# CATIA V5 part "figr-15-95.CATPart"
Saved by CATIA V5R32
Part number: Part1
Bounding box of the stored display mesh (mm): x -40 to 40, y -60 to 60, z -4 to 2
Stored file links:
  D:\PROJECTS\Project 2022\CATIA V5 6R 2022\Resources\Part Files\c15_catia_v5_6r2022_prt\figr-15-95.CATPart
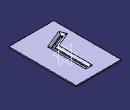
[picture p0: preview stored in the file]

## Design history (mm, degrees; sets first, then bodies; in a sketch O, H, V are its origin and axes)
SheetMetalParameters1: Thickness 2, BendRadius 4, KFactor 0.400515 {= log(min(100,max(20*SheetMetalParameters1.BendRadius,SheetMetalParameters1.Thickness)/SheetMetalParameters1.Thickness))/log(100)/2}, ReliefRadialLength 1, ReliefAxialLength 2, MinimumBendRadius 0
Body1 (main body)
  Sketch1 on xy-plane, origin (0, 0, 0), H (-1, 0, 0), V (0, -1, 0)
    line L1 (40, 60) -> (40, -60)
    line L2 (40, -60) -> (-40, -60)
    line L3 (-40, -60) -> (-40, 60)
    line L4 (-40, 60) -> (40, 60)
    length L4 = 80
    length L1 = 120
    vertical: L1 V, L3 V
    horizontal: L2 H, L4 H
    equidistance: L1 L3 O, L2 L4 O
  Wall1: Thickness 2, Profile Sketch1, OffsetValue 0
  Sketch2 on face of Wall1, origin (0, 0, 2), H (1, 0, 0), V (0, 1, 0)
    line L1 (0, 40.0798) -> (0, -21.0085)
    line L2 (0, -21.0085) -> (-27, -32)
    vertical: L1 V
  d_Stamp1: NewRoot_AttribNormalisation "No Standard", Stamp_FilletRadius 2, Stamp_IntersectFilletRadius 2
